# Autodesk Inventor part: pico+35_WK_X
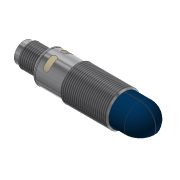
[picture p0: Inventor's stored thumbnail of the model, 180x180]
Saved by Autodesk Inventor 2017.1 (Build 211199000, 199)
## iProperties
Shininess: 20.0
Length Units: 11269
Angle Units: 11279
Time Units: 11290
Mass Units: 11283
Length Display Precision: 2
Angle Display Precision: 2
Part Number: pico+35_WK_X
Material: Nichtrostender Stahl - 440C
Document SubType Name: Modellieren
Description: Ipc-25 /CXX/M18
Checked By: Alves
Created: 2005-08
Designer: Ohle
Manufacturer: Standard
Standards Organization: Custom
Appearance: Aluminium - poliert
Density: 0.0
Volumn: 0.0
Area: 0.0
PropertySet Name: Model Information
Control State: 0
Master: False
Checked Out: False
BESTELLNUMMER: Ipc-25 /CXX/M18
ME: ST
Title: Ipc Sensoren
Author: Ohle
Comments: keine Bemerkung
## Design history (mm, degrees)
sketch "Skizze10"
  geometry: L1 (-43.018, 0)-(17.482, 0); L2 (-39.018, 6.5)-(-39.018, 7.25); L3 (-45.9, 8)-(-45.9, 8); L4 (-23.268, 9)-(0.232, 9); L5 (1.482, 0)-(-82.2, 0); L6 (-24.018, 8.25)-(-23.268, 9); L7 (0.982, 8.25)-(0.232, 9); L8 (-50.518, 6)-(-39.518, 6); L9 (-37.418, 8.25)-(-24.018, 8.25); L10 (-51.018, 4.5)-(-43.018, 4.5); L11 (-43.018, 0)-(-43.018, 4.5); L12 (-37.518, 8.25)-(-38.018, 8.25); L13 (-39.518, 6)-(-39.018, 6.5); L14 (-51.018, 5.5)-(-51.018, 4.5); L15 (-51.018, 5.5)-(-50.518, 6); L16 (-37.518, 8.25)-(-37.518, 8.15); L17 (-37.518, 8.15)-(-37.418, 8.15); L18 (-37.418, 8.15)-(-37.418, 8.25); L19 (0.982, 8.25)-(9.232, 8.25); L20 (17.482, 0)-(17.482, 0); A1 r 1 centre (-38.018, 7.25) between (-38.018, 8.25) and (-39.018, 7.25); A2 r 8.25 centre (9.232, 0) between (17.482, 0) and (9.232, 8.25); 4 further points
  constraints: 41 end point, 8 point on line, 5 parallel, 4 perpendicular, 4 point on circle, 4 tangent, 2 centre point, 2 horizontal, 1 collinear
  dimensions: "d171" = 4.5 distance between parallel lines of L10 L1; "d250" = 0.75 distance from line of L7.start L4; "d256" = 45 deg angle of L4 L6; "d257" = 8.25 distance between parallel lines of L5 L9; "d263" = 8.25 distance between parallel lines of L5 L12; "d266" = 12 distance from line of L2 L14.start; "d269" = 6 distance between parallel lines of L5 L8; "d289" = 135 deg angle of L7 L4; "d290" = 0.5 horizontal distance of L8.end L2.start; "d291" = 45 deg angle of L13 L8 (derived); "d293" = 0.5 horizontal distance of L14.start L8.start; "d294" = 45 deg angle of L15 L8 (derived); "d295" = 8 distance of L10.start L10.end; "d296" = 1.5 distance of L12.start point (-39.018, 8.25); "d297" = 0.1 distance of L16.end L17.end; "d298" = 8.15 distance between parallel lines of L17 L1; "d299" = 15 distance from line of L6.start L2; "d300" = 1 radius of A1; "d338" = 8.25 radius of A2; "d339" = 16.5 horizontal distance of L20.end L7.start; "d340" = 8.25 distance between parallel lines of L1 L19 (derived); "d365" = 25 distance of L7.start L6.start
revolve "Grundkörper pico+" sketch "Skizze10" stored, may be unused: angle "d168" = 90 deg
feature "Gewinde M12" dims "d174" = 10, "d175" = 0
feature "Gewinde M 18" dims "d179" = 10, "d180" = 0
workplane "Arbeitsebene1"
workplane "Arbeitsebene2"
sketch "Skizze13"
  geometry: L1 (-3.409, -3.409)-(3.61, 3.61); L2 (-3.439, 3.439)-(4.105, -4.105); L3 (-12.6, 0)-(12.6, 0) reference; C1 r 0.5 at (2.121, -2.121); C2 r 0.5 at (2.121, 2.121); C3 r 0.5 at (-2.121, 2.121); C4 r 0.5 at (-2.121, -2.121); C5 r 4.5 at (0, 0) reference; C6 r 0.5 at (0, 0); A1 r 3 centre (0, 0) between (-2.121, 2.121) and (2.121, 2.121); 2 further points
  constraints: 6 centre point, 6 point on line, 4 coincident, 4 end point, 4 equal radius, 4 point on circle, 1 horizontal alignment, 1 perpendicular
  dimensions: "d208" = 1 diameter of C3; "d209" = 6 diameter of A1
extrude "Pole" join sketch "Skizze13" distance "d212" = 7; taper "d213" = 0 deg
fillet "Rundung Pole" dims "d214" = 0.5
sketch "Skizze14"
  geometry: C1 r 0.5 at (0, -4.5); A1 r 4.5 centre (0, 0) between (4.435, -0.762) and (4.435, 0.762); A2 r 4.5 centre (0, 0) between (0, 4.5) and (0.499, 4.472) reference; A3 r 0.5 centre (0, 4.5) between (-0.499, 4.472) and (0.499, 4.472); 3 further points
  constraints: 9 point on circle, 3 centre point, 3 coincident, 1 horizontal alignment, 1 vertical alignment
  dimensions: "d215" = 9 diameter of A1; "d280" = 1 diameter of A3; "d330" = 1 diameter of C1
extrude "Verdrehsicherung" join sketch "Skizze14" distance "d217" = 7; taper "d218" = 0 deg
sketch "Skizze18"
  geometry: C1 r 7.25 at (0, 0) reference; C2 r 1 at (-8.15, 0)
  constraints: 1 centre point, 1 horizontal alignment
  dimensions: "d328" = 2 diameter of C2; "d329" = 8.15 distance of C1.centre C2.centre
extrude "Bohrung Ausrichtung" cut sketch "Skizze18" distance "d316" = 0.75; taper "d317" = 0 deg
workplane "Arbeitsebene4"
sketch "Skizze19"
  geometry: L1 (-39.018, 0)-(-30.18, 0); L2 (-34.718, -7.5)-(-34.718, -3); L3 (-31.718, -7.5)-(-31.718, -3); L4 (-31.718, 3)-(-31.718, 7.5); L5 (-34.718, 3)-(-34.718, 7.5); A1 r 1.5 centre (-33.218, 3) between (-31.718, 3) and (-34.718, 3); A2 r 1.5 centre (-33.218, -3) between (-34.718, -3) and (-31.718, -3); A3 r 1.5 centre (-33.218, 7.5) between (-31.718, 7.5) and (-34.718, 7.5); A4 r 1.5 centre (-33.218, -7.5) between (-34.718, -7.5) and (-31.718, -7.5); 4 further points; 1 other entity
  constraints: 10 end point, 8 point on circle, 8 tangent, 4 centre point, 3 equal radius, 2 vertical alignment, 1 horizontal, 2 other
  dimensions: "d319" = 3 diameter of A2; "d320" = 6 distance of A2.centre A1.centre; "d321" = 4.5 distance of A1.centre A3.centre; "d322" = 4.5 distance of A4.centre A2.centre; "d323" = 3 distance from line of A2.centre L1; "d324" = 5.8 dimension on A1.centre; "d325" = 5.8 dimension on A2.centre
feature "Prägen LED-Fenster" sketch "Skizze19" dims "d326" = 0.01, "d327" = 0
workplane "Arbeitsebene5"
sketch "Skizze20"
  geometry: L1 (9.232, -8.25)-(9.232, 8.25) reference; L2 (0.982, -8.25)-(0.982, 8.25) reference; L3 (9.232, -8.25)-(9.232, 8.25) reference; L4 (1.482, -8.25)-(18.508, -8.25); L5 (18.508, -8.25)-(18.508, 8.25); L6 (18.508, 8.25)-(1.482, 8.25); L7 (1.482, 8.25)-(1.482, -8.25)
  constraints: 8 end point, 2 parallel, 1 horizontal, 1 perpendicular
  dimensions: "d342" = 0.5 distance between parallel lines of L7 L2
extrude "USW-Fläche Winkelkopf" cut sketch "Skizze20" distance "d343" = 4.8; taper "d344" = 0 deg
sketch "Skizze21"
  geometry: C1 r 7 at (-9.232, 0); A1 r 7.494 centre (-9.232, 0) between (-9.232, 7.494) and (-9.232, -7.494) reference
  constraints: 1 centre point, 1 coincident
  dimensions: "d345" = 14 diameter of C1
extrude "Extrusion6" cut sketch "Skizze21" distance "d346" = 0.01; taper "d347" = 0 deg
sketch "Skizze22"
  geometry: C1 r 7 at (0, 0) reference; C2 r 4.8 at (0, 0)
  constraints: 1 centre point, 1 coincident
  dimensions: "d348" = 9.6 diameter of C2
extrude "Extrusion7" join sketch "Skizze22" distance "d349" = 0.01; taper "d350" = 0 deg
sketch "Skizze28"
  geometry: L1 (-0.982, 8.25)-(-9.232, 8.25) reference; L2 (-0.982, 8.25)-(-0.982, -8.25) reference; L3 (-9.232, -3.45)-(-16.726, -3.45) reference; L4 (-9.232, 8.15)-(-0.982, 8.15); A1 r 8.25 centre (-9.232, 0) between (-9.232, 8.25) and (-16.726, -3.45) reference; A2 r 8.15 centre (-9.232, 0) between (-9.232, 8.15) and (-16.616, -3.45)
  constraints: 2 end point, 2 point on circle, 2 point on line, 1 centre point, 1 coincident, 1 perpendicular, 1 tangent
  dimensions: "d362" = 0.1 radial gap between concentric circles of A2 A1
extrude "Extrusion8" cut sketch "Skizze28" stored distance "d363" = 0.3; taper "d364" = 0 deg
sketch "Skizze29"
  geometry: C1 r 5.5 at (0, 0); C2 r 4.5 at (0, 0); C3 r 4.15 at (0, 0); C4 r 5.25 at (0, 0); 2 further points
  constraints: 4 centre point
  dimensions: "d366" = 8.3 diameter of C3; "d367" = 10.5 diameter of C4
extrude "Extrusion9" join sketch "Skizze29" stored distance "d368" = 1; taper "d369" = 0 deg
sketch "Skizze30"
  geometry: C1 r 5.25 at (0, 0) reference; C2 r 7.839 at (0, 0); 1 further point
  constraints: 1 centre point
extrude "Extrusion10" cut sketch "Skizze30" distance "d370" = 2.6; taper "d371" = 0 deg
chamfer "Fase2" distance "d372" = 0.75; stored, may be unused: second distance "d373" = 2, angle "d374" = 30 deg
node "Volumenkörper1"
node "Volumenkörper"
node "Flächenkörper"
node "Projizierte Kontur2"
node "Projizierte Kontur3"
other parameters: "d10" = 14, "d73" = -35, "d130" = 0.2, "d207" = -95.5, "d318" = 8.25, "d341" = -8.25
